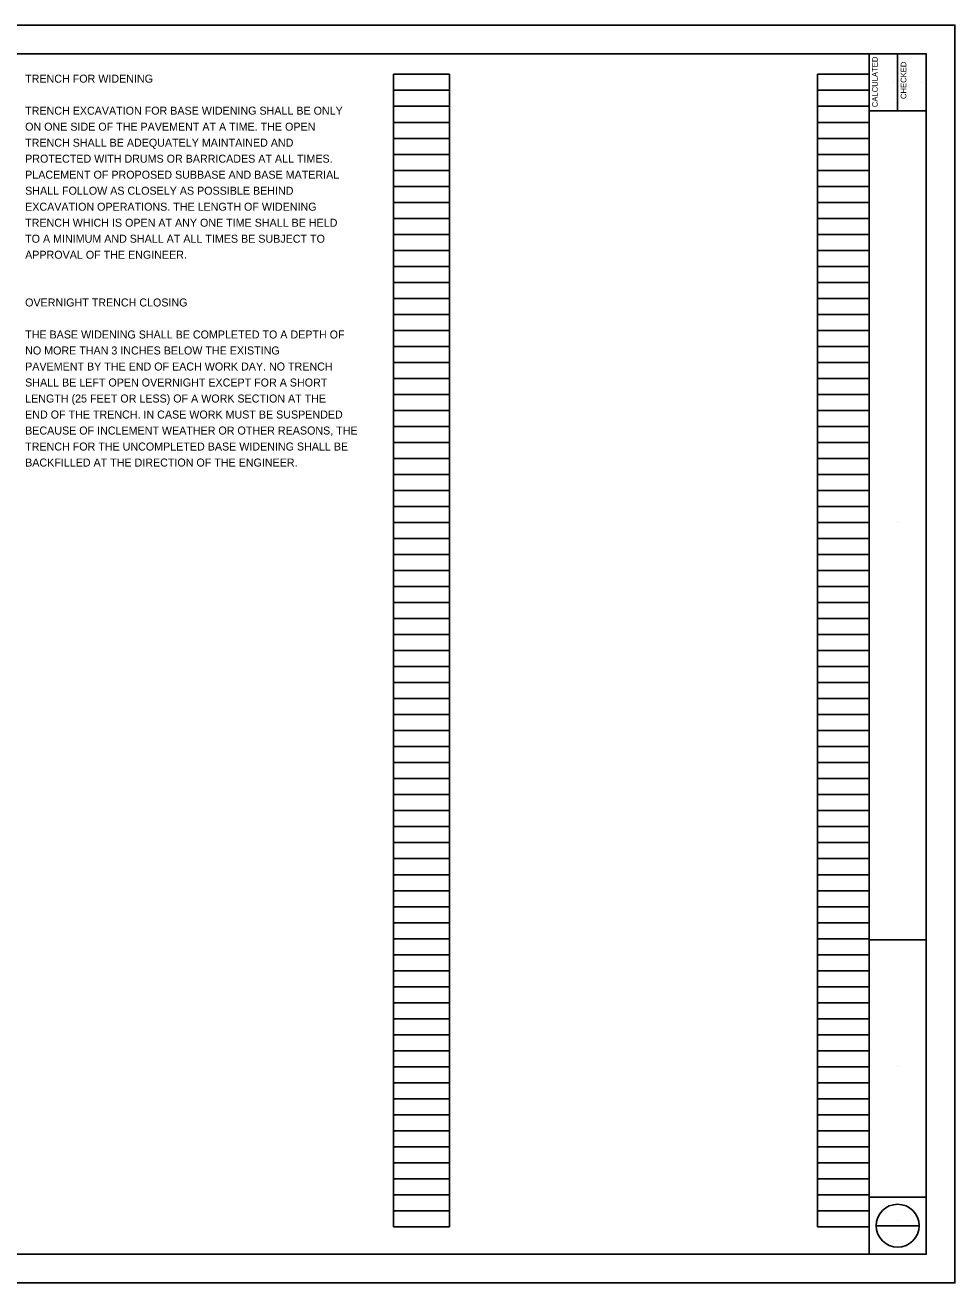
# Model space of a CAD drawing. Extents: x 0 to 34, y 0 to 22.
# Drawn here: x 17.74 to 34, y 0 to 22 of the extents above; entities that cross this region are included whole.
import ezdxf

# ---------------------------------------------------------------- set-up
doc = ezdxf.new("R2010")
doc.units = 0
for name, color, linetype in [('SH_Border', 7, 'Continuous'), ('SH_Cut_Line', 7, 'Continuous'), ('SH_Data', 7, 'Continuous'), ('SH_Text', 7, 'Continuous')]:
    doc.layers.add(name, color=color, linetype=linetype)

msp = doc.modelspace()

# ---------------------------------------------------------------- linework, layer by layer
at = {"layer": 'SH_Border'}
for p, q in [((32.5, 0.5), (32.5, 21.5)), ((33, 21.5), (33, 20.5)), ((32.5, 20.5), (33.5, 20.5)), ((32.5, 6), (33.5, 6)), ((32.5, 1.5), (33.5, 1.5))]:
    msp.add_line(p, q, dxfattribs=at)
msp.add_lwpolyline([(2, 21.5), (33.5, 21.5), (33.5, 0.5), (2, 0.5)], close=True, dxfattribs=at)
at = {"layer": 'SH_Cut_Line'}
msp.add_lwpolyline([(0, 0), (34, 0), (34, 22), (0, 22)], close=True, dxfattribs=at)
at = {"layer": 'SH_Data'}
for p, q in [((24.18, 0.98), (24.18, 21.14)), ((24.18, 21.14), (25.16, 21.14)), ((25.16, 0.98), (25.16, 21.14)), ((31.6, 0.98), (31.6, 21.14)), ((31.6, 21.14), (32.5, 21.14)), ((32.5, 0.98), (32.5, 21.14)), ((32.92, 21.004), (32.92, 21.004)), ((33.42, 21.004), (33.42, 21.004)), ((24.18, 20.86), (25.16, 20.86)), ((31.6, 20.86), (32.5, 20.86)), ((24.18, 20.58), (25.16, 20.58)), ((31.6, 20.58), (32.5, 20.58)), ((24.18, 20.3), (25.16, 20.3)), ((31.6, 20.3), (32.5, 20.3)), ((24.18, 20.02), (25.16, 20.02)), ((31.6, 20.02), (32.5, 20.02)), ((24.18, 19.74), (25.16, 19.74)), ((31.6, 19.74), (32.5, 19.74)), ((24.18, 19.46), (25.16, 19.46)), ((31.6, 19.46), (32.5, 19.46)), ((24.18, 19.18), (25.16, 19.18)), ((31.6, 19.18), (32.5, 19.18)), ((24.18, 18.9), (25.16, 18.9)), ((31.6, 18.9), (32.5, 18.9)), ((24.18, 18.62), (25.16, 18.62)), ((31.6, 18.62), (32.5, 18.62)), ((24.18, 18.34), (25.16, 18.34)), ((31.6, 18.34), (32.5, 18.34)), ((24.18, 18.06), (25.16, 18.06)), ((31.6, 18.06), (32.5, 18.06)), ((24.18, 17.78), (25.16, 17.78)), ((31.6, 17.78), (32.5, 17.78)), ((24.18, 17.5), (25.16, 17.5)), ((31.6, 17.5), (32.5, 17.5)), ((24.18, 17.22), (25.16, 17.22)), ((31.6, 17.22), (32.5, 17.22)), ((24.18, 16.94), (25.16, 16.94)), ((31.6, 16.94), (32.5, 16.94)), ((24.18, 16.66), (25.16, 16.66)), ((31.6, 16.66), (32.5, 16.66)), ((24.18, 16.38), (25.16, 16.38)), ((31.6, 16.38), (32.5, 16.38)), ((24.18, 16.1), (25.16, 16.1)), ((31.6, 16.1), (32.5, 16.1)), ((24.18, 15.82), (25.16, 15.82)), ((31.6, 15.82), (32.5, 15.82)), ((24.18, 15.54), (25.16, 15.54)), ((31.6, 15.54), (32.5, 15.54)), ((24.18, 15.26), (25.16, 15.26)), ((31.6, 15.26), (32.5, 15.26)), ((24.18, 14.98), (25.16, 14.98)), ((31.6, 14.98), (32.5, 14.98)), ((24.18, 14.7), (25.16, 14.7)), ((31.6, 14.7), (32.5, 14.7)), ((24.18, 14.42), (25.16, 14.42)), ((31.6, 14.42), (32.5, 14.42)), ((24.18, 14.14), (25.16, 14.14)), ((31.6, 14.14), (32.5, 14.14)), ((24.18, 13.86), (25.16, 13.86)), ((31.6, 13.86), (32.5, 13.86)), ((24.18, 13.58), (25.16, 13.58)), ((31.6, 13.58), (32.5, 13.58)), ((24.18, 13.3), (25.16, 13.3)), ((31.6, 13.3), (32.5, 13.3)), ((33, 13.292), (33, 13.292)), ((24.18, 13.02), (25.16, 13.02)), ((31.6, 13.02), (32.5, 13.02)), ((24.18, 12.74), (25.16, 12.74)), ((31.6, 12.74), (32.5, 12.74)), ((24.18, 12.46), (25.16, 12.46)), ((31.6, 12.46), (32.5, 12.46)), ((24.18, 12.18), (25.16, 12.18)), ((31.6, 12.18), (32.5, 12.18)), ((24.18, 11.9), (25.16, 11.9)), ((31.6, 11.9), (32.5, 11.9)), ((24.18, 11.62), (25.16, 11.62)), ((31.6, 11.62), (32.5, 11.62)), ((24.18, 11.34), (25.16, 11.34)), ((31.6, 11.34), (32.5, 11.34)), ((24.18, 11.06), (25.16, 11.06)), ((31.6, 11.06), (32.5, 11.06)), ((24.18, 10.78), (25.16, 10.78)), ((31.6, 10.78), (32.5, 10.78)), ((24.18, 10.5), (25.16, 10.5)), ((31.6, 10.5), (32.5, 10.5)), ((24.18, 10.22), (25.16, 10.22)), ((31.6, 10.22), (32.5, 10.22)), ((24.18, 9.94), (25.16, 9.94)), ((31.6, 9.94), (32.5, 9.94)), ((24.18, 9.66), (25.16, 9.66)), ((31.6, 9.66), (32.5, 9.66)), ((24.18, 9.38), (25.16, 9.38)), ((31.6, 9.38), (32.5, 9.38)), ((24.18, 9.1), (25.16, 9.1)), ((31.6, 9.1), (32.5, 9.1)), ((24.18, 8.82), (25.16, 8.82)), ((31.6, 8.82), (32.5, 8.82)), ((24.18, 8.54), (25.16, 8.54)), ((31.6, 8.54), (32.5, 8.54)), ((24.18, 8.26), (25.16, 8.26)), ((31.6, 8.26), (32.5, 8.26)), ((24.18, 7.98), (25.16, 7.98)), ((31.6, 7.98), (32.5, 7.98)), ((24.18, 7.7), (25.16, 7.7)), ((31.6, 7.7), (32.5, 7.7)), ((24.18, 7.42), (25.16, 7.42)), ((31.6, 7.42), (32.5, 7.42)), ((24.18, 7.14), (25.16, 7.14)), ((31.6, 7.14), (32.5, 7.14)), ((24.18, 6.86), (25.16, 6.86)), ((31.6, 6.86), (32.5, 6.86)), ((24.18, 6.58), (25.16, 6.58)), ((31.6, 6.58), (32.5, 6.58)), ((24.18, 6.3), (25.16, 6.3)), ((31.6, 6.3), (32.5, 6.3)), ((24.18, 6.02), (25.16, 6.02)), ((31.6, 6.02), (32.5, 6.02)), ((24.18, 5.74), (25.16, 5.74)), ((31.6, 5.74), (32.5, 5.74)), ((24.18, 5.46), (25.16, 5.46)), ((31.6, 5.46), (32.5, 5.46)), ((24.18, 5.18), (25.16, 5.18)), ((31.6, 5.18), (32.5, 5.18)), ((24.18, 4.9), (25.16, 4.9)), ((31.6, 4.9), (32.5, 4.9)), ((24.18, 4.62), (25.16, 4.62)), ((31.6, 4.62), (32.5, 4.62)), ((24.18, 4.34), (25.16, 4.34)), ((31.6, 4.34), (32.5, 4.34)), ((24.18, 4.06), (25.16, 4.06)), ((31.6, 4.06), (32.5, 4.06)), ((24.18, 3.78), (25.16, 3.78)), ((31.6, 3.78), (32.5, 3.78)), ((33, 3.792), (33, 3.792)), ((24.18, 3.5), (25.16, 3.5)), ((31.6, 3.5), (32.5, 3.5)), ((24.18, 3.22), (25.16, 3.22)), ((31.6, 3.22), (32.5, 3.22)), ((24.18, 2.94), (25.16, 2.94)), ((31.6, 2.94), (32.5, 2.94)), ((24.18, 2.66), (25.16, 2.66)), ((31.6, 2.66), (32.5, 2.66)), ((24.18, 2.38), (25.16, 2.38)), ((31.6, 2.38), (32.5, 2.38)), ((24.18, 2.1), (25.16, 2.1)), ((31.6, 2.1), (32.5, 2.1)), ((24.18, 1.82), (25.16, 1.82)), ((31.6, 1.82), (32.5, 1.82)), ((24.18, 1.54), (25.16, 1.54)), ((31.6, 1.54), (32.5, 1.54)), ((24.18, 1.26), (25.16, 1.26)), ((31.6, 1.26), (32.5, 1.26)), ((24.18, 0.98), (25.16, 0.98)), ((31.6, 0.98), (32.5, 0.98)), ((32.625, 1), (33.375, 1)), ((33, 1.085), (33, 1.085)), ((33, 0.745), (33, 0.745))]:
    msp.add_line(p, q, dxfattribs=at)
msp.add_circle((33, 1), 0.375, dxfattribs=at)

# ---------------------------------------------------------------- texts
for s, p in [('CALCULATED', (32.652, 20.565)), ('CHECKED', (33.152, 20.708))]:
    msp.add_text(s, height=0.1, rotation=90, dxfattribs=at).set_placement(p)
at = {"layer": 'SH_Text'}
for s, p in [('TRENCH FOR WIDENING', (17.74, 20.994)), ('TRENCH EXCAVATION FOR BASE WIDENING SHALL BE ONLY', (17.74, 20.434)), ('ON ONE SIDE OF THE PAVEMENT AT A TIME. THE OPEN', (17.74, 20.154)), ('TRENCH SHALL BE ADEQUATELY MAINTAINED AND', (17.74, 19.874)), ('PROTECTED WITH DRUMS OR BARRICADES AT ALL TIMES.', (17.74, 19.594)), ('PLACEMENT OF PROPOSED SUBBASE AND BASE MATERIAL', (17.74, 19.314)), ('SHALL FOLLOW AS CLOSELY AS POSSIBLE BEHIND', (17.74, 19.034)), ('EXCAVATION OPERATIONS. THE LENGTH OF WIDENING', (17.74, 18.754)), ('TRENCH WHICH IS OPEN AT ANY ONE TIME SHALL BE HELD', (17.74, 18.474)), ('TO A MINIMUM AND SHALL AT ALL TIMES BE SUBJECT TO', (17.74, 18.194)), ('APPROVAL OF THE ENGINEER.', (17.74, 17.914)), ('OVERNIGHT TRENCH CLOSING', (17.74, 17.079)), ('THE BASE WIDENING SHALL BE COMPLETED TO A DEPTH OF', (17.74, 16.519)), ('NO MORE THAN 3 INCHES BELOW THE EXISTING', (17.74, 16.239)), ('PAVEMENT BY THE END OF EACH WORK DAY. NO TRENCH', (17.74, 15.959)), ('SHALL BE LEFT OPEN OVERNIGHT EXCEPT FOR A SHORT', (17.74, 15.679)), ('LENGTH (25 FEET OR LESS) OF A WORK SECTION AT THE', (17.74, 15.399)), ('END OF THE TRENCH. IN CASE WORK MUST BE SUSPENDED', (17.74, 15.119)), ('BECAUSE OF INCLEMENT WEATHER OR OTHER REASONS, THE', (17.74, 14.839)), ('TRENCH FOR THE UNCOMPLETED BASE WIDENING SHALL BE', (17.74, 14.559)), ('BACKFILLED AT THE DIRECTION OF THE ENGINEER.', (17.74, 14.279))]:
    msp.add_text(s, height=0.14, dxfattribs=at).set_placement(p)

doc.saveas('drawing.dxf')
